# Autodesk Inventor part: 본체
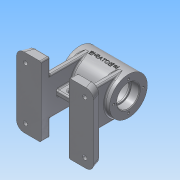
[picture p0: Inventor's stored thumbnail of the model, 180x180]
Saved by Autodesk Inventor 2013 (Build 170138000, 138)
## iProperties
Created: 2016-07
Part Number: 본체
Material: 알루미늄 6061
Document SubType Name: Modeling
Designer: Administrator
Density: 2.71 g/cm^3
Mass: 520.161 g
Surface Area: 548.131 cm^2
Volume: 191.941 cm^3
Author: Administrator
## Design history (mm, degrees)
sketch "스케치1"
  geometry: L1 (-35, 0)-(35, 0); L2 (-35, 0)-(-35, 27); L3 (-35, 27)-(35, 27); L4 (35, 27)-(35, 0); 2 further points
  constraints: 8 end point, 2 perpendicular, 1 coincident, 1 horizontal, 1 midpoint, 1 parallel
  dimensions: "d1" = 70 distance of L1.start L1.end; "d3" = 54 diameter of L3 L1
revolve "회전1" sketch "스케치1" stored, may be unused: angle "d4" = 90 deg
sketch "스케치2"
  geometry: L1 (-35, -27)-(-35, 27) reference; L2 (-35, 27)-(35, 27) reference; L3 (35, 27)-(35, -27) reference; L4 (35, -27)-(-35, -27) reference; L5 (-35, 0)-(35, 0); L6 (-35, 0)-(-35, 16); L7 (-35, 16)-(-23, 16); L8 (-23, 16)-(-23, 14); L9 (-23, 14)-(-21, 14); L10 (-21, 14)-(-21, 22); L11 (-21, 22)-(21, 22); L12 (21, 22)-(21, 14); L13 (21, 14)-(23, 14); L14 (23, 14)-(23, 16); L15 (23, 16)-(35, 16); L16 (35, 0)-(35, 16); 1 further point
  constraints: 24 end point, 6 parallel, 3 perpendicular, 2 midpoint, 2 point on line, 1 collinear
  dimensions: "d7" = 32 diameter of L7 L5; "d9" = 28 diameter of L9 L5; "d10" = 44 diameter of L11 L5; "d11" = 28 diameter of L13 L5; "d12" = 32 diameter of L15 L5; "d13" = 12 distance between parallel lines of L8 L6; "d14" = 2 distance between parallel lines of L10 L8; "d15" = 42 distance between parallel lines of L12 L10; "d16" = 2 distance between parallel lines of L14 L12
revolve "회전2" sketch "스케치2" stored, may be unused: angle "d17" = 90 deg
fillet "모깎기1" dims "d18" = 2
fillet "모깎기2" dims "d19" = 0.3
chamfer "모따기1" distance "d20" = 1; stored, may be unused: second distance "d21" = 2, angle "d22" = 45 deg
node "작업 평면1"
sketch "스케치3"
  geometry: L1 (35, 27)-(35, -27) reference; C1 r 5 at (13, 0); 1 further point
  constraints: 1 centre point, 1 horizontal alignment
  dimensions: "d24" = 10 diameter of C1; "d25" = 22 distance from line of C1.centre L1
extrude "돌출1" join sketch "스케치3" stored distance "d26" = 10; taper "d27" = 0 deg
fillet "모깎기3" dims "d28" = 2
sketch "스케치4"
  geometry: L1 (0, 0)-(-27, 0); L2 (0, 0)-(-25.441, -15.898)
  constraints: 4 end point, 1 horizontal
  dimensions: "d29" = 30 distance of L1.start L2.end; "d30" = 32 deg angle of L2 L1
node "작업 평면2"
sketch "스케치5"
  geometry: C1 r 6 at (0, 0); 1 further point
  constraints: 1 centre point, 1 coincident
  dimensions: "d31" = 12 diameter of C1
extrude "돌출2" join sketch "스케치5" stored distance "d32" = 10; taper "d33" = 0 deg
sketch "스케치15"
  geometry: C1 r 27 at (0, 0) reference; 1 further point
  constraints: 1 vertical alignment
  dimensions: "d63" = 21 distance of C1.centre point (0, 21)
hole "구멍1" sketch "스케치15" at (0, 21) diameter "d64" = 3.242; stored, may be unused: countersink angle "d68" = 90 deg, drill point angle "d70" = 118 deg; dims "d65" = 8, "d66" = 4, "d67" = 2, "d69" = 10
hole "구멍2" diameter "d76" = 5.188; stored, may be unused: countersink angle "d80" = 90 deg, drill point angle "d82" = 118 deg; dims "d74" = 10, "d75" = 10, "d77" = 8, "d78" = 4, "d79" = 2, "d81" = 10
hole "구멍3" diameter "d85" = 5.188; stored, may be unused: countersink angle "d89" = 90 deg, drill point angle "d91" = 118 deg; dims "d83" = 10, "d84" = 10, "d86" = 8, "d87" = 4, "d88" = 2, "d90" = 10
sketch "스케치20"
  geometry: L1 (20, -57)-(20, -70); L2 (20, -70)-(55, -70); L3 (55, -70)-(50.268, -57); L4 (50.268, -57)-(20, -57); 1 further point
  constraints: 8 end point, 2 perpendicular, 1 vertical
  dimensions: "d111" = 70 distance from line of L2 point (0, 0); "d112" = 55 horizontal distance of L2.end point (0, 0); "d113" = 35 distance from line of L2.end L1; "d114" = 13 distance between parallel lines of L2 L4; "d115" = 110 deg angle of L2 L3
extrude "돌출7" join sketch "스케치20" stored distance "d116" = 100; taper "d117" = 0 deg
sketch "스케치21"
  geometry: L1 (0, 0)-(0, 100) reference; L2 (8, 77)-(0, 77); L3 (0, 77)-(0, 23); L4 (0, 23)-(8, 23); L5 (8, 23)-(8, 77); 1 further point
  constraints: 8 end point, 2 parallel, 1 horizontal, 1 perpendicular, 1 point on line
  dimensions: "d118" = 8 distance between parallel lines of L3 L5; "d120" = 27 distance from line of point (-20, 50) L2; "d121" = 54 distance between parallel lines of L4 L2
extrude "돌출8" join sketch "스케치21" stored distance "d122" = 100; taper "d123" = 0 deg
fillet "모깎기4" dims "d124" = 10
fillet "모깎기5" dims "d125" = 2
fillet "모깎기6" dims "d126" = 2
fillet "모깎기7" dims "d127" = 2
sketch "스케치22"
  geometry: L1 (-20, -48)-(20, -48); L2 (-10.406, 22)-(-10.406, 30) reference; L3 (-10.406, 30)-(-8, 30) reference; L4 (-8, 30)-(-8, 29) reference; L5 (-6, 27)-(35, 27) reference; L6 (35, 27)-(35, 22.621) reference; L7 (35, 22.621)-(25, 22.621) reference; L8 (25, 22.621)-(24.026, 21) reference; L9 (24.026, 21)-(25, 19.379) reference; L10 (25, 19.379)-(35, 19.379) reference; L11 (35, 19.379)-(35, 17) reference; L12 (35, 17)-(34, 16) reference; L13 (34, 16)-(23.3, 16) reference; L14 (23, 15.7)-(23, 14) reference; L15 (23, 14)-(21, 14) reference; L16 (21, 14)-(21, 20) reference; L17 (19, 22)-(-10.406, 22) reference; L18 (-35, -17)-(-34, -16) reference; L19 (-34, -16)-(-23.3, -16) reference; L20 (-23, -15.7)-(-23, -14) reference; L21 (-23, -14)-(-21, -14) reference; L22 (-21, -14)-(-21, -20) reference; L23 (-19, -22)-(19, -22) reference; L24 (21, -20)-(21, -14) reference; L25 (21, -14)-(23, -14) reference; L26 (23, -14)-(23, -15.7) reference; L27 (23.3, -16)-(34, -16) reference; L28 (34, -16)-(35, -17) reference; L29 (35, -17)-(35, -19.379) reference; L30 (35, -19.379)-(25, -19.379) reference; L31 (25, -19.379)-(24.026, -21) reference; L32 (24.026, -21)-(25, -22.621) reference; L33 (25, -22.621)-(35, -22.621) reference; L34 (35, -22.621)-(35, -27) reference; L35 (35, -27)-(30, -27) reference; L36 (28, -29)-(28, -55) reference; L37 (30, -57)-(48.868, -57) reference; L38 (50.747, -58.316)-(55, -70) reference; L39 (55, -70)-(20, -70) reference; L40 (20, -70)-(20, -29) reference; L41 (18, -27)-(-18, -27) reference; L42 (-20, -29)-(-20, -70) reference; L43 (-20, -70)-(-55, -70) reference; L44 (-55, -70)-(-50.747, -58.316) reference; L45 (-48.868, -57)-(-30, -57) reference; L46 (-28, -55)-(-28, -29) reference; L47 (-30, -27)-(-35, -27) reference; L48 (-35, -27)-(-35, -22.621) reference; L49 (-35, -22.621)-(-25, -22.621) reference; L50 (-25, -22.621)-(-24.026, -21) reference; L51 (-24.026, -21)-(-25, -19.379) reference; L52 (-25, -19.379)-(-35, -19.379) reference; L53 (-35, -19.379)-(-35, -17) reference; L54 (-34, 16)-(-35, 17) reference; L55 (-35, 17)-(-35, 19.379) reference; L56 (-35, 19.379)-(-25, 19.379) reference; L57 (-25, 19.379)-(-24.026, 21) reference; L58 (-24.026, 21)-(-25, 22.621) reference; L59 (-25, 22.621)-(-35, 22.621) reference; L60 (-35, 22.621)-(-35, 27) reference; L61 (-35, 27)-(-20, 27) reference; L62 (-18, 29)-(-18, 30) reference; L63 (-18, 30)-(-15.594, 30) reference; L64 (-15.594, 30)-(-15.594, 22) reference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; A1 r 0.3 centre (23.3, 15.7) between (23.3, 16) and (23, 15.7) reference; A2 r 2 centre (19, 20) between (21, 20) and (19, 22) reference; A3 r 0.3 centre (-23.3, -15.7) between (-23.3, -16) and (-23, -15.7) reference; A4 r 2 centre (-19, -20) between (-21, -20) and (-19, -22) reference; A5 r 2 centre (19, -20) between (19, -22) and (21, -20) reference; A6 r 0.3 centre (23.3, -15.7) between (23, -15.7) and (23.3, -16) reference; A7 r 2 centre (30, -29) between (30, -27) and (28, -29) reference; A8 r 2 centre (30, -55) between (28, -55) and (30, -57) reference; A9 r 2 centre (48.868, -59) between (50.747, -58.316) and (48.868, -57) reference; A10 r 2 centre (18, -29) between (20, -29) and (18, -27) reference; A11 r 2 centre (-18, -29) between (-18, -27) and (-20, -29) reference; A12 r 2 centre (-48.868, -59) between (-48.868, -57) and (-50.747, -58.316) reference; A13 r 2 centre (-30, -55) between (-30, -57) and (-28, -55) reference; A14 r 2 centre (-30, -29) between (-28, -29) and (-30, -27) reference; A15 r 2 centre (-19, 20) between (-19, 22) and (-21, 20) reference; A16 r 0.3 centre (-23.3, 15.7) between (-23, 15.7) and (-23.3, 16) reference; 1 further point
  constraints: 2 end point, 1 horizontal, 2 other
  dimensions: "d128" = 21 distance between parallel lines of L1 L47
feature "리브1" sketch "스케치22" dims "d129" = 1, "d130" = 8, "d131" = 0, "d132" = 0, "d133" = 1, "d134" = 1
sketch "스케치23"
  geometry: L1 (40, 19.277)-(40, 0) reference; L2 (2, 21.298)-(38, 21.298) reference; L3 (0, 0)-(0, 19.277) reference; L4 (40, 0)-(0, 0) reference; 1 further point
  constraints: 2 other
fillet "모깎기8" dims "d135" = 2
fillet "모깎기9" dims "d136" = 2
sketch "스케치24"
  geometry: L1 (-11.5, -34.5)-(11.5, -34.5); L2 (11.5, -34.5)-(11.5, -41.5); L3 (11.5, -41.5)-(-11.5, -41.5); L4 (-11.5, -41.5)-(-11.5, -34.5); L5 (-11.5, -38)-(11.5, -38); L6 (44.358, -70)-(22, -70) reference; 1 further point
  constraints: 10 end point, 2 midpoint, 2 parallel, 1 horizontal, 1 perpendicular
  dimensions: "d137" = 11.5 distance from line of point (0, 0) L4; "d138" = 23 distance between parallel lines of L2 L4; "d139" = 3.5 distance between parallel lines of L5 L1; "d140" = 32 distance between parallel lines of L6 L5
extrude "돌출9" cut sketch "스케치24" stored distance "d141" = 100; taper "d142" = 0 deg
fillet "모깎기10" dims "d143" = 3.5
fillet "모깎기11" dims "d144" = 2
node "작업 평면5"
sketch "스케치25"
  geometry: L1 (-35, -27)-(-35, 27) reference; 2 further points
  constraints: 1 coincident, 1 other
  dimensions: "d145" = 35 distance from line of L1 point (0, 0) (derived); "d146" = 27 vertical distance of L1.end point (0, 0)
feature "엠보싱1" sketch "스케치25" dims "d12" = 32, "d147" = 0.5, "d148" = 0
sketch "스케치26"
  geometry: L1 (8.513, -10)-(26.868, -10) reference; 3 further points
  dimensions: "d153" = 12.5 distance from line of point (6.368, 2.5) L1; "d154" = 75 distance of point (6.368, 77.5) point (6.368, 2.5); "d155" = 42.5 horizontal distance of point (48.868, 40) point (6.368, 2.5); "d156" = 42.5 horizontal distance of point (48.868, 40) point (6.368, 77.5)
hole "구멍4" sketch "스케치26" at (6.368, 77.5), (6.368, 2.5) diameter "d157" = 6; stored, may be unused: countersink angle "d161" = 90 deg, drill point angle "d163" = 0 deg; dims "d158" = 8, "d159" = 10, "d160" = 4, "d162" = 10
node "솔리드1"
pattern_circular "원형 패턴1" dims angle "d72" = 360 deg
mirror "대칭2"
mirror "대칭3"
mirror "대칭4"
mirror "대칭5"
node "절단 모서리 투영1"
node "절단 모서리 투영4"
